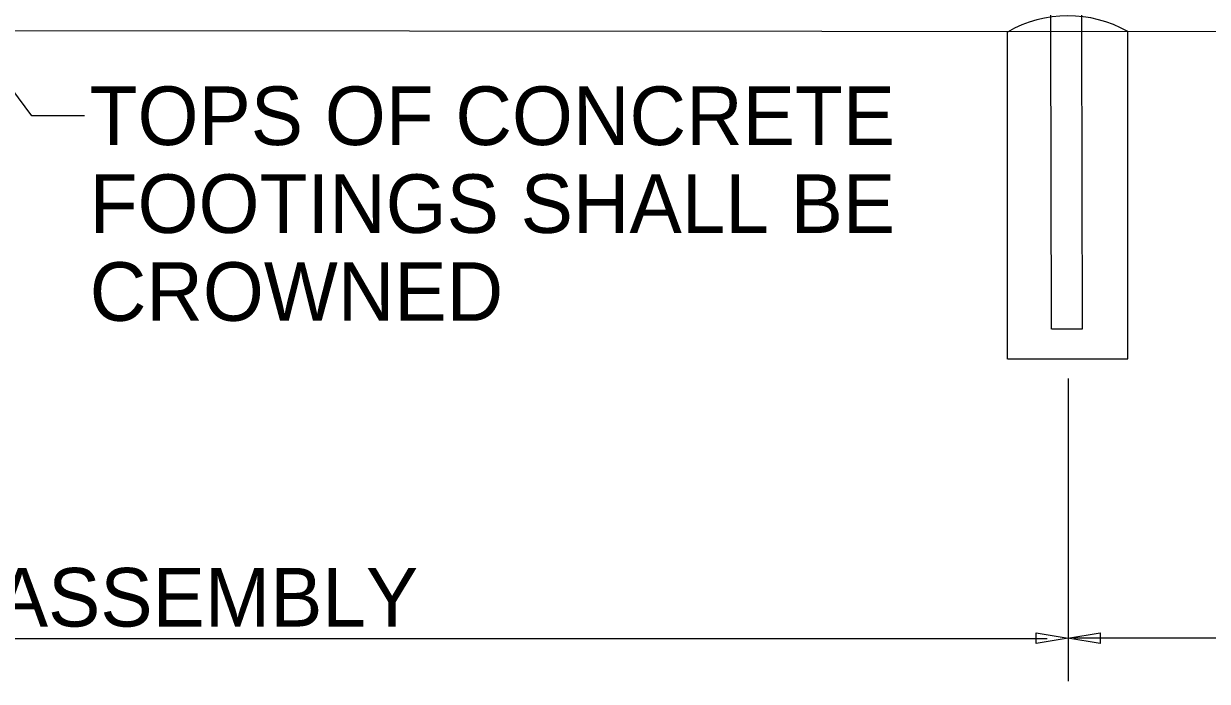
# Model space of a CAD drawing. Extents: x 0 to 2.85, y -0.1 to 1.83.
# Drawn here: x 0.5717 to 0.7737, y 1.171 to 1.2832 of the extents above; entities that cross this region are included whole.
import ezdxf

# ---------------------------------------------------------------- set-up
doc = ezdxf.new("R2010")
doc.units = 0
for name, color, linetype in [('CT_CSHT_GeneralLabel', 7, 'Continuous'), ('CT_Dimensions', 7, 'Continuous'), ('sb_Chainlink Fence', 7, 'Continuous'), ('sb_Earth', 7, 'Continuous'), ('sb_Existing Concrete', 7, 'Continuous'), ('sb_Existing Structural Steel', 7, 'Continuous')]:
    doc.layers.add(name, color=color, linetype=linetype)

msp = doc.modelspace()

# ---------------------------------------------------------------- linework, layer by layer
at = {"layer": 'CT_Dimensions'}
for p, q in [((0.74997, 1.22268), (0.74997, 1.17099)), ((0.36289, 1.17828), (0.74643, 1.17828)), ((0.75095, 1.1784), (0.94362, 1.1784))]:
    msp.add_line(p, q, dxfattribs=at)
for points in [[(0.74452, 1.17929), (0.75002, 1.17838), (0.74452, 1.17746)], [(0.75544, 1.17745), (0.74995, 1.17837), (0.75544, 1.17928)]]:
    msp.add_lwpolyline(points, close=True, dxfattribs=at)
at = {"layer": 'sb_Chainlink Fence'}
for p, q in [((0.5731, 1.26752), (0.56224, 1.28213)), ((0.58212, 1.26752), (0.5731, 1.26752))]:
    msp.add_line(p, q, dxfattribs=at)
at = {"layer": 'sb_Earth'}
msp.add_line((0.36814, 1.28227), (0.79423, 1.28187), dxfattribs=at)
at = {"layer": 'sb_Existing Concrete'}
for p, q in [((0.73965, 1.22599), (0.73965, 1.2818)), ((0.76016, 1.22606), (0.76016, 1.28188)), ((0.73969, 1.22606), (0.76017, 1.22606))]:
    msp.add_line(p, q, dxfattribs=at)
msp.add_arc((0.74997, 1.26398), 0.0206, 60.3466, 120.0812, dxfattribs=at)
at = {"layer": 'sb_Existing Structural Steel'}
for p, q in [((0.74706, 1.28188), (0.74714, 1.40433)), ((0.75235, 1.28192), (0.75246, 1.40436)), ((0.74714, 1.23112), (0.74706, 1.28188)), ((0.75246, 1.23115), (0.75235, 1.28192)), ((0.74722, 1.23115), (0.75246, 1.23115))]:
    msp.add_line(p, q, dxfattribs=at)

# ---------------------------------------------------------------- texts
at = {"layer": 'CT_CSHT_GeneralLabel'}
msp.add_text('TERMINAL POST ASSEMBLY', height=0.01, dxfattribs=at).set_placement((0.45552, 1.18034))
at = {"layer": 'CT_Dimensions'}
for s, p in [('TOPS OF CONCRETE', (0.583, 1.26252)), ('FOOTINGS SHALL BE ', (0.583, 1.24752)), ('CROWNED', (0.583, 1.23252))]:
    msp.add_text(s, height=0.01, dxfattribs=at).set_placement(p)

doc.saveas('drawing.dxf')
